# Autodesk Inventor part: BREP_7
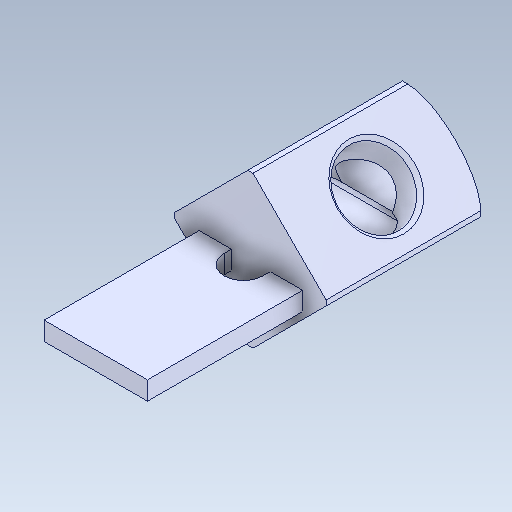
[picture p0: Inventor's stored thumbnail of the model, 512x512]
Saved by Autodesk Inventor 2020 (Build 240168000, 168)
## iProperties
Created: 2017-09
Part Number: BREP_7
Material: Générique
Document SubType Name: Modeling
Designer: bruno
Density: 1 g/cm^3
Appearance: Par défaut
Author: bruno
Sending System: SolidWorks 2016
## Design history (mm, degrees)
feature "Importée1"
node "Solide1"
